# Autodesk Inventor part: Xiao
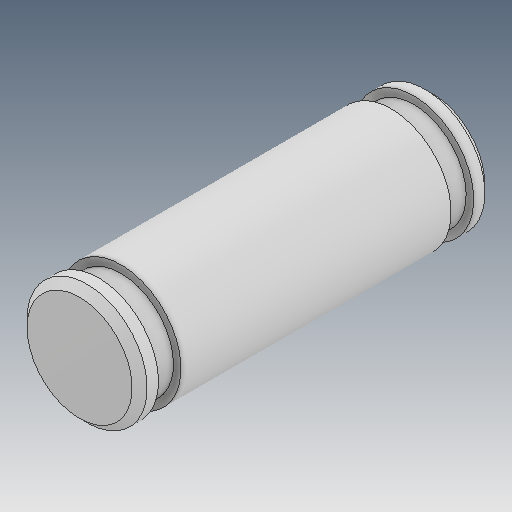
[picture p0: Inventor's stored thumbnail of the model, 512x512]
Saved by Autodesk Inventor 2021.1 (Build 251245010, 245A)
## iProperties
Created: 2021-05
Part Number: Xiao
Material: Ogólny
Document SubType Name: Modeling
Designer: user
Density: 1 g/cm^3
Appearance: Domyślna
Author: user
Revision Number: ÈÎºÎ
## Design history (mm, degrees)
feature "ÊäÈë1"
node "Bryła1"
